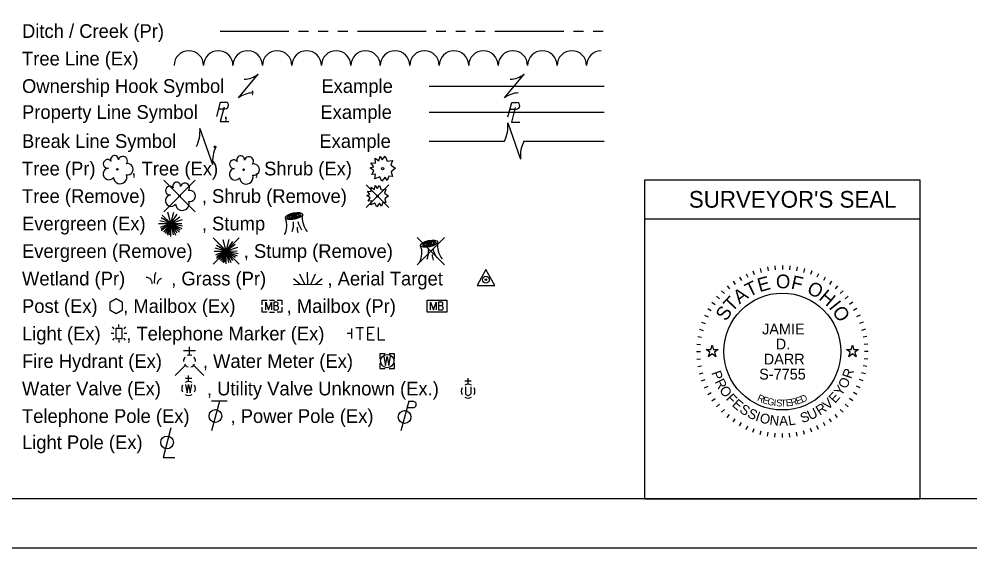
# Model space of a CAD drawing. Extents: x 0 to 34, y 0 to 22.
# Drawn here: x 8.23 to 17.92, y 0 to 5.39 of the extents above; entities that cross this region are included whole.
import ezdxf

# ---------------------------------------------------------------- set-up
doc = ezdxf.new("R2010")
doc.units = 0
for name, color, linetype in [('SH_Border', 7, 'Continuous'), ('SH_Cut_Line', 7, 'Continuous'), ('SH_Data', 7, 'Continuous'), ('SH_Seal', 7, 'Continuous'), ('SH_Text', 7, 'Continuous')]:
    doc.layers.add(name, color=color, linetype=linetype)

msp = doc.modelspace()

# ---------------------------------------------------------------- linework, layer by layer
at = {"layer": 'SH_Border'}
msp.add_lwpolyline([(1.5, 21.5), (33.5, 21.5), (33.5, 0.5), (1.5, 0.5)], close=True, dxfattribs=at)
at = {"layer": 'SH_Cut_Line'}
msp.add_lwpolyline([(0, 0), (34, 0), (34, 22), (0, 22)], close=True, dxfattribs=at)
at = {"layer": 'SH_Data'}
for p, q in [((14.6061, 3.75), (17.4061, 3.75)), ((14.6061, 0.5), (14.6061, 3.75)), ((17.4061, 3.75), (17.4061, 0.5)), ((14.6061, 3.35), (17.4061, 3.35)), ((14.6061, 0.5), (17.4061, 0.5))]:
    msp.add_line(p, q, dxfattribs=at)
at = {"layer": 'SH_Seal'}
for p, q in [((15.7069, 2.8222), (15.7205, 2.7846)), ((15.7797, 2.8452), (15.79, 2.8065)), ((15.8542, 2.8617), (15.8611, 2.8223)), ((15.9299, 2.8717), (15.9333, 2.8318)), ((16.0061, 2.875), (16.0061, 2.835)), ((16.0824, 2.8717), (16.0789, 2.8318)), ((16.1581, 2.8617), (16.1511, 2.8223)), ((16.2326, 2.8452), (16.2222, 2.8065)), ((16.3054, 2.8222), (16.2917, 2.7846)), ((15.5042, 2.7168), (15.5272, 2.684)), ((15.5686, 2.7578), (15.5886, 2.7231)), ((15.6363, 2.793), (15.6532, 2.7568)), ((16.3759, 2.793), (16.359, 2.7568)), ((16.4436, 2.7578), (16.4236, 2.7231)), ((16.508, 2.7168), (16.4851, 2.684)), ((15.3874, 2.6187), (15.4157, 2.5904)), ((15.4437, 2.6703), (15.4694, 2.6396)), ((16.5686, 2.6703), (16.5428, 2.6396)), ((16.6248, 2.6187), (16.5966, 2.5904)), ((15.3358, 2.5624), (15.3665, 2.5367)), ((16.6764, 2.5624), (16.6458, 2.5367)), ((15.2483, 2.4375), (15.283, 2.4175)), ((15.2894, 2.5019), (15.3221, 2.4789)), ((16.7229, 2.5019), (16.6901, 2.4789)), ((16.7639, 2.4375), (16.7293, 2.4175)), ((15.2131, 2.3698), (15.2494, 2.3529)), ((16.7991, 2.3698), (16.7629, 2.3529)), ((15.1839, 2.2993), (15.2215, 2.2856)), ((16.8284, 2.2993), (16.7908, 2.2856)), ((15.1444, 2.1519), (15.1838, 2.145)), ((15.1609, 2.2265), (15.1996, 2.2161)), ((16.8513, 2.2265), (16.8127, 2.2161)), ((16.8678, 2.1519), (16.8284, 2.145)), ((15.1345, 2.0763), (15.1743, 2.0728)), ((16.8778, 2.0763), (16.8379, 2.0728)), ((15.1311, 2), (15.1711, 2)), ((16.8811, 2), (16.8411, 2)), ((15.1345, 1.9237), (15.1743, 1.9272)), ((15.1444, 1.8481), (15.1838, 1.855)), ((16.8678, 1.8481), (16.8284, 1.855)), ((16.8778, 1.9237), (16.8379, 1.9272)), ((15.1609, 1.7735), (15.1996, 1.7839)), ((16.8513, 1.7735), (16.8127, 1.7839)), ((15.1839, 1.7007), (15.2215, 1.7144)), ((15.2131, 1.6302), (15.2494, 1.6471)), ((16.7991, 1.6302), (16.7629, 1.6471)), ((16.8284, 1.7007), (16.7908, 1.7144)), ((15.2483, 1.5625), (15.283, 1.5825)), ((16.7639, 1.5625), (16.7293, 1.5825)), ((15.2894, 1.4981), (15.3221, 1.5211)), ((15.3358, 1.4376), (15.3665, 1.4633)), ((16.6764, 1.4376), (16.6458, 1.4633)), ((16.7229, 1.4981), (16.6901, 1.5211)), ((15.3874, 1.3813), (15.4157, 1.4096)), ((15.4437, 1.3297), (15.4694, 1.3604)), ((16.5686, 1.3297), (16.5428, 1.3604)), ((16.6248, 1.3813), (16.5966, 1.4096)), ((15.5042, 1.2832), (15.5272, 1.316)), ((15.5686, 1.2422), (15.5886, 1.2769)), ((16.4436, 1.2422), (16.4236, 1.2769)), ((16.508, 1.2832), (16.4851, 1.316)), ((15.6363, 1.207), (15.6532, 1.2432)), ((15.7069, 1.1778), (15.7205, 1.2154)), ((15.7797, 1.1548), (15.79, 1.1935)), ((15.8542, 1.1383), (15.8611, 1.1777)), ((15.9299, 1.1283), (15.9333, 1.1682)), ((16.0061, 1.125), (16.0061, 1.165)), ((16.0824, 1.1283), (16.0789, 1.1682)), ((16.1581, 1.1383), (16.1511, 1.1777)), ((16.2326, 1.1548), (16.2222, 1.1935)), ((16.3054, 1.1778), (16.2917, 1.2154)), ((16.3759, 1.207), (16.359, 1.2432))]:
    msp.add_line(p, q, dxfattribs=at)
for points in [[(15.2297, 2.02), (15.2766, 2.02), (15.2911, 2.0645), (15.3056, 2.02), (15.3525, 2.02), (15.3146, 1.9924), (15.3291, 1.9478), (15.2911, 1.9754), (15.2531, 1.9478), (15.2676, 1.9924)], [(16.6597, 2.02), (16.7066, 2.02), (16.7211, 2.0645), (16.7356, 2.02), (16.7825, 2.02), (16.7446, 1.9924), (16.7591, 1.9478), (16.7211, 1.9754), (16.6831, 1.9478), (16.6976, 1.9924)]]:
    msp.add_lwpolyline(points, close=True, dxfattribs=at)
msp.add_circle((16.0061, 2), 0.595, dxfattribs=at)
at = {"layer": 'SH_Text'}
for p, q in [((10.28, 5.2634), (10.98, 5.2634)), ((11.08, 5.2634), (11.18, 5.2634)), ((11.28, 5.2634), (11.38, 5.2634)), ((11.48, 5.2634), (11.58, 5.2634)), ((11.68, 5.2634), (12.38, 5.2634)), ((12.48, 5.2634), (12.58, 5.2634)), ((12.68, 5.2634), (12.78, 5.2634)), ((12.88, 5.2634), (12.98, 5.2634)), ((13.08, 5.2634), (13.78, 5.2634)), ((13.88, 5.2634), (13.98, 5.2634)), ((14.08, 5.2634), (14.18, 5.2634)), ((10.4674, 4.5834), (10.6674, 4.8234)), ((13.1756, 4.5834), (13.3756, 4.8234)), ((10.5674, 4.7034), (10.5674, 4.7034)), ((12.4101, 4.7034), (14.1924, 4.7034)), ((13.2756, 4.7034), (13.2756, 4.7034)), ((10.2676, 4.4724), (10.3325, 4.4724)), ((13.2333, 4.4683), (13.2981, 4.4683)), ((10.3077, 4.4412), (10.3077, 4.4412)), ((12.4101, 4.4388), (14.1924, 4.4388)), ((13.2734, 4.4371), (13.2734, 4.4371)), ((10.0749, 4.2719), (10.2049, 3.9037)), ((13.2106, 4.3276), (13.3406, 3.9593)), ((10.1399, 4.0878), (10.1399, 4.0878)), ((12.4101, 4.1434), (13.1757, 4.1434)), ((13.2756, 4.1435), (13.2756, 4.1435)), ((13.3755, 4.1434), (14.1924, 4.1434)), ((9.7078, 3.7437), (10.0285, 3.423)), ((10.0285, 3.7437), (9.7078, 3.423)), ((11.7669, 3.6993), (11.9986, 3.4675)), ((11.9986, 3.6993), (11.7669, 3.4675)), ((9.8681, 3.5834), (9.8681, 3.5834)), ((11.8827, 3.5834), (11.8827, 3.5834)), ((9.7786, 3.3032), (9.6914, 3.3903)), ((9.7786, 3.3032), (9.7477, 3.4185)), ((9.7786, 3.3032), (9.81, 3.4206)), ((9.7786, 3.3032), (9.845, 3.4003)), ((9.6552, 3.3032), (9.7786, 3.3032)), ((9.7786, 3.3032), (9.6683, 3.3327)), ((9.7786, 3.3032), (9.6714, 3.2641)), ((9.7786, 3.3032), (9.679, 3.2461)), ((9.7786, 3.3032), (9.681, 3.3606)), ((9.7786, 3.3032), (9.681, 3.2283)), ((9.7786, 3.3032), (9.705, 3.2165)), ((9.7786, 3.3032), (9.7207, 3.2028)), ((9.7786, 3.3032), (9.737, 3.1947)), ((9.7786, 3.3032), (9.747, 3.1817)), ((9.7786, 3.3032), (9.7651, 3.1884)), ((9.7786, 3.3032), (9.87, 3.3733)), ((9.7786, 3.3032), (9.897, 3.3433)), ((9.7786, 3.3032), (9.8914, 3.3055)), ((9.7786, 3.1722), (9.7786, 3.3032)), ((9.7786, 3.3032), (9.8017, 3.1872)), ((9.7786, 3.3032), (9.827, 3.1865)), ((9.7786, 3.3032), (9.842, 3.2083)), ((9.7786, 3.3032), (9.8683, 3.2151)), ((9.7786, 3.3032), (9.8742, 3.2393)), ((9.7786, 3.3032), (9.8902, 3.2546)), ((9.7786, 3.3032), (9.8993, 3.2792)), ((11.0523, 3.3034), (11.0523, 3.3034)), ((10.209, 3.157), (10.4763, 2.8897)), ((10.4763, 3.157), (10.209, 2.8897)), ((10.3426, 3.0234), (10.2554, 3.1106)), ((10.3426, 3.0234), (10.3118, 3.1387)), ((10.3426, 3.0234), (10.3741, 3.1408)), ((10.3426, 3.0234), (10.409, 3.1205)), ((12.2888, 3.1624), (12.5669, 2.8843)), ((12.5669, 3.1624), (12.2888, 2.8843)), ((10.2193, 3.0234), (10.3426, 3.0234)), ((10.3426, 3.0234), (10.2323, 3.053)), ((10.3426, 3.0234), (10.2354, 2.9843)), ((10.3426, 3.0234), (10.2431, 2.9663)), ((10.3426, 3.0234), (10.245, 3.0808)), ((10.3426, 3.0234), (10.245, 2.9485)), ((10.3426, 3.0234), (10.269, 2.9367)), ((10.3426, 3.0234), (10.2847, 2.923)), ((10.3426, 3.0234), (10.301, 2.9149)), ((10.3426, 3.0234), (10.3111, 2.902)), ((10.3426, 3.0234), (10.3291, 2.9086)), ((10.3426, 3.0234), (10.4341, 3.0935)), ((10.3426, 3.0234), (10.4611, 3.0636)), ((10.3426, 3.0234), (10.4554, 3.0257)), ((10.3426, 2.8924), (10.3426, 3.0234)), ((10.3426, 3.0234), (10.3657, 2.9075)), ((10.3426, 3.0234), (10.391, 2.9067)), ((10.3426, 3.0234), (10.4061, 2.9286)), ((10.3426, 3.0234), (10.4323, 2.9353)), ((10.3426, 3.0234), (10.4382, 2.9595)), ((10.3426, 3.0234), (10.4543, 2.9748)), ((10.3426, 3.0234), (10.4633, 2.9994)), ((10.3426, 3.0234), (10.3426, 3.0234)), ((12.4278, 3.0234), (12.4278, 3.0234)), ((12.4279, 3.0234), (12.4279, 3.0234)), ((11.1742, 2.6834), (11.1724, 2.8089)), ((11.0956, 2.6822), (11.0273, 2.7393)), ((11.1443, 2.683), (11.0921, 2.789)), ((11.2042, 2.6838), (11.2532, 2.7914)), ((11.253, 2.6846), (11.3195, 2.7437)), ((11.0281, 2.6812), (11.3203, 2.6856)), ((10.7854, 2.5245), (10.8355, 2.5245)), ((10.811, 2.4634), (10.811, 2.4634)), ((12.4891, 2.4634), (12.4891, 2.4634)), ((10.7854, 2.4023), (10.8355, 2.4023)), ((9.2031, 2.2318), (9.1846, 2.2506)), ((9.2513, 2.2474), (9.2513, 2.274)), ((9.318, 2.2506), (9.2994, 2.2318)), ((11.624, 2.1334), (11.624, 2.2334)), ((9.1992, 2.1837), (9.1726, 2.1837)), ((9.2031, 2.135), (9.1846, 2.1162)), ((9.2513, 2.1834), (9.2513, 2.1834)), ((9.318, 2.1162), (9.2994, 2.135)), ((9.3301, 2.1837), (9.3034, 2.1837)), ((11.624, 2.1834), (11.5742, 2.1834)), ((9.2513, 2.1194), (9.2513, 2.0928)), ((9.9694, 1.9636), (9.9694, 2.0496)), ((10.0294, 2.0066), (9.9094, 2.0066)), ((9.9271, 1.861), (9.8231, 1.7571)), ((9.9694, 1.9034), (9.9694, 1.9034)), ((9.9694, 1.9034), (9.9694, 1.9034)), ((10.0117, 1.861), (10.1157, 1.7571)), ((11.983, 1.9034), (11.983, 1.9034)), ((9.9603, 1.6934), (9.9603, 1.757)), ((9.992, 1.7252), (9.9285, 1.7252)), ((12.8382, 1.6988), (12.7746, 1.6988)), ((12.8065, 1.667), (12.8065, 1.7305)), ((9.9603, 1.6234), (9.9603, 1.6234)), ((12.7793, 1.6401), (12.7793, 1.5712)), ((12.8065, 1.597), (12.8065, 1.597)), ((12.8335, 1.6401), (12.8335, 1.5712)), ((10.2733, 1.4934), (10.193, 1.1934)), ((10.3533, 1.4934), (10.1933, 1.4934)), ((12.2023, 1.4934), (12.122, 1.1934)), ((12.2023, 1.4934), (12.2448, 1.4934)), ((12.1852, 1.4296), (12.2448, 1.4296))]:
    msp.add_line(p, q, dxfattribs=at)
for points in [[(10.2466, 4.3928), (10.2857, 4.5411), (10.3374, 4.541)], [(10.3211, 4.4892), (10.2815, 4.3414), (10.3688, 4.3414)], [(13.2123, 4.3887), (13.2514, 4.537), (13.303, 4.5369)], [(13.2867, 4.4851), (13.2471, 4.3373), (13.3344, 4.3373)], [(11.9315, 3.9539), (11.9617, 3.9906), (11.9825, 3.938), (12.0371, 3.947), (12.0201, 3.8964), (12.0674, 3.8666), (12.0246, 3.8299), (12.0371, 3.7842), (11.9994, 3.7876), (11.9831, 3.742), (11.9617, 3.7766), (11.9278, 3.7357), (11.9064, 3.7801), (11.8554, 3.7586), (11.865, 3.8056), (11.8244, 3.8015), (11.8481, 3.841), (11.8096, 3.8694), (11.8466, 3.8826), (11.8162, 3.9227), (11.8628, 3.9172), (11.8613, 3.9691), (11.899, 3.9407), (11.9093, 3.99), (11.9315, 3.9539)], [(11.8791, 3.6603), (11.9049, 3.6916), (11.9225, 3.6468), (11.9689, 3.6544), (11.9545, 3.6114), (11.9947, 3.5862), (11.9583, 3.5549), (11.9689, 3.5161), (11.9369, 3.519), (11.9231, 3.4802), (11.9049, 3.5096), (11.876, 3.4749), (11.8578, 3.5126), (11.8145, 3.4943), (11.8226, 3.5343), (11.7881, 3.5308), (11.8082, 3.5643), (11.7756, 3.5885), (11.807, 3.5997), (11.7812, 3.6338), (11.8208, 3.6291), (11.8195, 3.6733), (11.8515, 3.6491), (11.8603, 3.691), (11.8791, 3.6603)], [(9.1581, 2.4259), (9.223, 2.3884), (9.288, 2.4259), (9.288, 2.5009), (9.223, 2.5384), (9.1581, 2.5009), (9.1581, 2.4259)], [(10.711, 2.476), (10.711, 2.5245), (10.7595, 2.5245)], [(10.8613, 2.5245), (10.911, 2.5245), (10.911, 2.476)], [(10.7595, 2.4023), (10.711, 2.4023), (10.711, 2.4508)], [(10.7462, 2.4234), (10.7462, 2.5034), (10.7751, 2.4234), (10.8029, 2.5034), (10.8029, 2.4234)], [(10.8621, 2.4669), (10.8652, 2.47), (10.8671, 2.4719), (10.8684, 2.4738), (10.869, 2.475), (10.8703, 2.4776), (10.8709, 2.4795), (10.8722, 2.4839), (10.8722, 2.4858), (10.8722, 2.4883), (10.8715, 2.4921), (10.8703, 2.4952), (10.8684, 2.4977), (10.8652, 2.5002), (10.8627, 2.5015), (10.8614, 2.5021), (10.8583, 2.5034), (10.8274, 2.5034), (10.8274, 2.4234), (10.8621, 2.4234), (10.8665, 2.4259), (10.8703, 2.4291), (10.8734, 2.4341), (10.8753, 2.4398), (10.8759, 2.4454), (10.8759, 2.4492), (10.8747, 2.453), (10.8722, 2.4587), (10.869, 2.4624), (10.8621, 2.4669), (10.8274, 2.4669)], [(10.911, 2.4508), (10.911, 2.4023), (10.8613, 2.4023)], [(12.4243, 2.4234), (12.4243, 2.5034), (12.4533, 2.4234), (12.481, 2.5034), (12.481, 2.4234)], [(12.5402, 2.4669), (12.5433, 2.47), (12.5452, 2.4719), (12.5465, 2.4738), (12.5471, 2.475), (12.5484, 2.4776), (12.549, 2.4795), (12.5503, 2.4839), (12.5503, 2.4858), (12.5503, 2.4883), (12.5496, 2.4921), (12.5484, 2.4952), (12.5465, 2.4977), (12.5433, 2.5002), (12.5408, 2.5015), (12.5396, 2.5021), (12.5364, 2.5034), (12.5056, 2.5034), (12.5056, 2.4234), (12.5402, 2.4234), (12.5446, 2.4259), (12.5484, 2.4291), (12.5515, 2.4341), (12.5534, 2.4398), (12.5541, 2.4454), (12.5541, 2.4492), (12.5528, 2.453), (12.5503, 2.4587), (12.5471, 2.4624), (12.5402, 2.4669), (12.5056, 2.4669)], [(11.6648, 2.2455), (11.7426, 2.2455)], [(11.7042, 2.2455), (11.7042, 2.1205)], [(11.8498, 2.2455), (11.7819, 2.2455), (11.7819, 2.1205), (11.8547, 2.1205)], [(11.8892, 2.2455), (11.8892, 2.1205), (11.9571, 2.1205)], [(11.7819, 2.1835), (11.8301, 2.1835)], [(11.963, 1.9784), (11.908, 1.9784), (11.908, 1.9234)], [(11.9497, 1.9484), (11.9663, 1.8584), (11.983, 1.9484), (11.9997, 1.8584), (12.0163, 1.9484)], [(12.058, 1.9234), (12.058, 1.9784), (12.003, 1.9784)], [(11.908, 1.8834), (11.908, 1.8284), (11.963, 1.8284)], [(12.003, 1.8284), (12.058, 1.8284), (12.058, 1.8834)], [(9.9285, 1.6644), (9.9444, 1.5782), (9.9603, 1.6644), (9.9763, 1.5782), (9.9921, 1.6644)], [(9.7806, 1.2221), (9.7018, 0.9229), (9.82, 0.9229)]]:
    msp.add_lwpolyline(points, dxfattribs=at)
for points in [[(12.8973, 2.6734), (13.0773, 2.6734), (12.9873, 2.8344)], [(12.3891, 2.5245), (12.5891, 2.5245), (12.5891, 2.4023), (12.3891, 2.4023)], [(9.218, 2.1334), (9.2846, 2.1334), (9.2846, 2.2334), (9.218, 2.2334)]]:
    msp.add_lwpolyline(points, close=True, dxfattribs=at)
for centre, radius in [((11.9357, 3.8634), 0.0115), ((9.2351, 3.8553), 0.0084), ((10.5197, 3.8518), 0.0072), ((9.8681, 3.5834), 0.0072), ((11.8827, 3.5834), 0.00979), ((12.9873, 2.7312), 0.035), ((12.9873, 2.7312), 0.008), ((11.983, 1.9034), 0.0675), ((10.2332, 1.3434), 0.065), ((12.1595, 1.3334), 0.065), ((9.7412, 1.0745), 0.065)]:
    msp.add_circle(centre, radius, dxfattribs=at)
for centre, radius, start, end in [((9.9624, 4.9134), 0.15, 0.00982, 179.99264), ((10.2623, 4.9134), 0.15, 0.00982, 179.99264), ((10.5623, 4.9134), 0.15, 0.00982, 179.99264), ((10.8623, 4.9134), 0.15, 0.00982, 179.99264), ((11.1623, 4.9134), 0.15, 0.00982, 179.99264), ((11.4623, 4.9134), 0.15, 0.00982, 179.99264), ((11.7623, 4.9134), 0.15, 0.00982, 179.99264), ((12.0623, 4.9134), 0.15, 0.00982, 179.99264), ((12.3623, 4.9134), 0.15, 0.00982, 179.99264), ((12.6623, 4.9134), 0.15, 0.00982, 179.99264), ((12.9623, 4.9134), 0.15, 0.00982, 179.99264), ((13.2623, 4.9134), 0.15, 0.00982, 179.99264), ((13.5623, 4.9134), 0.15, 0.00982, 179.99264), ((13.8623, 4.9134), 0.15, 0.00982, 179.99264), ((14.1623, 4.9134), 0.15, 89.99552, 179.99264), ((10.5092, 5.0383), 0.2668, 273.69448, 306.33701), ((13.2175, 5.0383), 0.2668, 273.69448, 306.33701), ((10.6255, 4.3684), 0.2668, 93.69448, 126.33701), ((13.3337, 4.3684), 0.2668, 93.69448, 126.33701), ((10.3322, 4.5069), 0.0345, 270.47098, 81.3281), ((13.2978, 4.5028), 0.0345, 270.47098, 81.3281), ((9.743, 4.2395), 0.3335, 332.94224, 5.58476), ((12.8786, 4.2951), 0.3335, 332.94224, 5.58476), ((10.5369, 3.9362), 0.3335, 152.94224, 185.58476), ((13.6725, 3.9918), 0.3335, 152.94224, 185.58476), ((9.2056, 3.9563), 0.0395, 354.0047, 205.97412), ((9.2899, 3.9402), 0.0466, 323.82996, 165.0376), ((10.4902, 3.9529), 0.0395, 354.0047, 205.97412), ((10.5745, 3.9367), 0.0466, 323.82996, 165.0376), ((9.1358, 3.9112), 0.0441, 39.06254, 279.54124), ((9.3389, 3.8564), 0.0574, 259.14531, 101.45961), ((10.4204, 3.9077), 0.0441, 39.06254, 279.54124), ((10.6235, 3.8529), 0.0574, 259.14531, 101.45961), ((9.1495, 3.8088), 0.0592, 96.17219, 320.57371), ((9.2635, 3.7771), 0.0685, 184.94757, 19.45715), ((10.4341, 3.8054), 0.0592, 96.17219, 320.57371), ((10.5481, 3.7737), 0.0685, 184.94757, 19.45715), ((9.7688, 3.6393), 0.0441, 39.06254, 279.54124), ((9.8386, 3.6844), 0.0395, 354.0047, 205.97412), ((9.9229, 3.6682), 0.0466, 323.82996, 165.0376), ((9.7825, 3.5369), 0.0592, 96.17219, 320.57371), ((9.9719, 3.5844), 0.0574, 259.14531, 101.45961), ((9.8965, 3.5052), 0.0685, 184.94757, 19.45715), ((11.3325, 3.3604), 0.2146, 171.41061, 219.91939), ((10.7607, 3.2861), 0.2001, 331.53375, 20.92689), ((10.7764, 3.3047), 0.2527, 340.79377, 3.54808), ((11.3777, 3.4062), 0.316, 194.9653, 212.12159), ((11.2475, 3.2634), 0.1819, 178.79264, 197.12241), ((12.7081, 3.0804), 0.2146, 171.41061, 219.91939), ((12.1363, 3.0061), 0.2001, 331.53375, 20.92689), ((12.152, 3.0247), 0.2527, 340.79377, 3.54808), ((12.7532, 3.1262), 0.316, 194.9653, 212.12159), ((12.6231, 2.9834), 0.1819, 178.79264, 197.12241), ((9.9694, 1.9034), 0.06, 140.02099, 184.06293), ((9.9694, 1.9034), 0.06, 68.13946, 112.03798), ((9.9694, 1.9034), 0.06, 356.01648, 39.98885), ((9.9694, 1.9034), 0.06, 211.87877, 255.84793), ((9.9694, 1.9034), 0.06, 283.82389, 329.90967), ((9.9603, 1.6235), 0.07, 150.01836, 209.98164), ((9.9603, 1.6235), 0.07, 60.01836, 120.01574), ((9.9603, 1.6235), 0.07, 330.01836, 29.98164), ((12.8064, 1.597), 0.07, 60.01836, 120.01574), ((9.9603, 1.6235), 0.07, 239.98426, 299.98164), ((12.8064, 1.597), 0.07, 150.01836, 209.98164), ((12.8064, 1.5839), 0.03, 205.19243, 334.80757), ((12.8064, 1.597), 0.07, 330.01836, 29.98164), ((12.2454, 1.4615), 0.0319, 268.8767, 91.1233), ((12.8064, 1.597), 0.07, 239.98426, 299.98164)]:
    msp.add_arc(centre, radius, start, end, dxfattribs=at)
for centre, major_axis in [((11.0335, 3.3789), (0.0868, 0.0187)), ((11.0335, 3.3789), (0.0651, 0.0141)), ((11.0335, 3.3789), (0.0488, 0.0105)), ((11.0335, 3.3789), (0.0275, 0.0059)), ((11.0335, 3.3789), (0.0154, 0.0033)), ((12.4091, 3.0989), (0.0868, 0.0187)), ((12.4091, 3.0989), (0.0651, 0.0141)), ((12.4091, 3.0989), (0.0488, 0.0105)), ((12.4091, 3.0989), (0.0275, 0.0059)), ((12.4091, 3.0989), (0.0154, 0.0033))]:
    msp.add_ellipse(centre, major_axis=major_axis, ratio=0.36865, dxfattribs=at)
for points in [[(9.5274, 2.759), (9.5688, 2.7413), (9.5865, 2.688)], [(9.6147, 2.692), (9.6147, 2.7393), (9.6206, 2.7837), (9.6294, 2.8045)], [(9.6424, 2.6848), (9.6543, 2.7232), (9.6838, 2.747)]]:
    msp.add_spline(points, degree=3, dxfattribs=at)

# ---------------------------------------------------------------- texts
at = {"layer": 'SH_Data'}
msp.add_text("SURVEYOR'S SEAL", height=0.17, dxfattribs=at).set_placement((15.054, 3.465))
at = {"layer": 'SH_Seal'}
for s, height, rotation, p in [('T', 0.14, 25.71674, (15.6678, 2.5518)), ('E', 0.14, 15.75706, (15.7745, 2.6038)), ('O', 0.14, 359.78119, (15.9408, 2.6443)), ('F', 0.14, 347.43619, (16.0872, 2.6417)), ('A', 0.14, 36.47472, (15.5695, 2.4781)), ('O', 0.14, 332.25863, (16.2459, 2.6015)), ('H', 0.14, 319.91363, (16.3693, 2.5361)), ('T', 0.14, 46.4344, (15.4944, 2.3964)), ('I', 0.14, 308.36695, (16.4726, 2.4483)), ('S', 0.14, 57.19238, (15.4342, 2.3014)), ('O', 0.14, 303.14906, (16.5083, 2.4089)), ('P', 0.1, 289.74314, (15.2815, 1.7841)), ('R', 0.1, 70.983, (16.707, 1.7167)), ('R', 0.1, 296.98022, (15.3154, 1.6927)), ('Y', 0.1, 55.50576, (16.6061, 1.54)), ('O', 0.1, 62.74284, (16.6562, 1.6133)), ('O', 0.1, 304.7158, (15.3593, 1.6079)), ('F', 0.1, 312.95596, (15.4254, 1.5158)), ('R', 0.07, 334.48695, (15.7436, 1.5051)), ('D', 0.07, 23.30524, (16.2071, 1.477)), ('E', 0.1, 48.26868, (16.5427, 1.4673)), ('E', 0.1, 319.68845, (15.4869, 1.4504)), ('S', 0.1, 326.92553, (15.5616, 1.3885)), ('E', 0.07, 341.03996, (15.7968, 1.4801)), ('G', 0.07, 347.47515, (15.8476, 1.4618)), ('I', 0.07, 353.78581, (15.9152, 1.4468)), ('S', 0.07, 356.89262, (15.9419, 1.4429)), ('T', 0.07, 3.00609, (15.9918, 1.4387)), ('E', 0.07, 6.01169, (16.0451, 1.4412)), ('R', 0.07, 11.91844, (16.0986, 1.4474)), ('E', 0.07, 17.68363, (16.1559, 1.4602)), ('R', 0.1, 33.29603, (16.3876, 1.3473)), ('V', 0.1, 41.03161, (16.4676, 1.4007)), ('S', 0.1, 334.16261, (15.6421, 1.3374)), ('I', 0.1, 341.39968, (15.7252, 1.2979)), ('O', 0.1, 345.13508, (15.7679, 1.2821)), ('S', 0.1, 18.32337, (16.2066, 1.2711)), ('U', 0.1, 25.56045, (16.2894, 1.2986)), ('N', 0.1, 353.37524, (15.8721, 1.2555)), ('A', 0.1, 1.11082, (15.9753, 1.2443)), ('L', 0.1, 8.3479, (16.0725, 1.2467))]:
    msp.add_text(s, height=height, rotation=rotation, dxfattribs=at).set_placement(p)
for s, p in [('JAMIE', (15.7998, 2.1749)), ('D.', (15.9393, 2.0216)), ('DARR', (15.8171, 1.8684)), ('S-7755', (15.7704, 1.7151))]:
    msp.add_text(s, height=0.11, dxfattribs=at).set_placement(p)
at = {"layer": 'SH_Text'}
for s, p in [('Ditch / Creek (Pr)', (8.2638, 5.1934)), ('Tree Line (Ex)', (8.2638, 4.9134)), ('Ownership Hook Symbol     ,             Example', (8.2638, 4.6334)), ('Property Line Symbol     ,                  Example', (8.2638, 4.3688)), ('Break Line Symbol       ,                    Example', (8.2638, 4.0734)), ('Tree (Pr)       , Tree (Ex)       , Shrub (Ex)', (8.2638, 3.7934)), ('Tree (Remove)           , Shrub (Remove)', (8.2638, 3.5134)), ('Evergreen (Ex)           , Stump ', (8.2638, 3.2334)), ('Evergreen (Remove)          , Stump (Remove)', (8.2638, 2.9534)), ('Wetland (Pr)         , Grass (Pr)            , Aerial Target    ', (8.2638, 2.6734)), ('Post (Ex)     , Mailbox (Ex)          , Mailbox (Pr)', (8.2638, 2.3934)), ('Light (Ex)     , Telephone Marker (Ex)     ', (8.2638, 2.1134)), ('Fire Hydrant (Ex)        , Water Meter (Ex)', (8.2638, 1.8334)), ('Water Valve (Ex)         , Utility Valve Unknown (Ex.)', (8.2638, 1.5534)), ('Telephone Pole (Ex)        , Power Pole (Ex)', (8.2638, 1.2734)), ('Light Pole (Ex)     ', (8.2638, 1.0063))]:
    msp.add_text(s, height=0.14, dxfattribs=at).set_placement(p)

doc.saveas('drawing.dxf')
